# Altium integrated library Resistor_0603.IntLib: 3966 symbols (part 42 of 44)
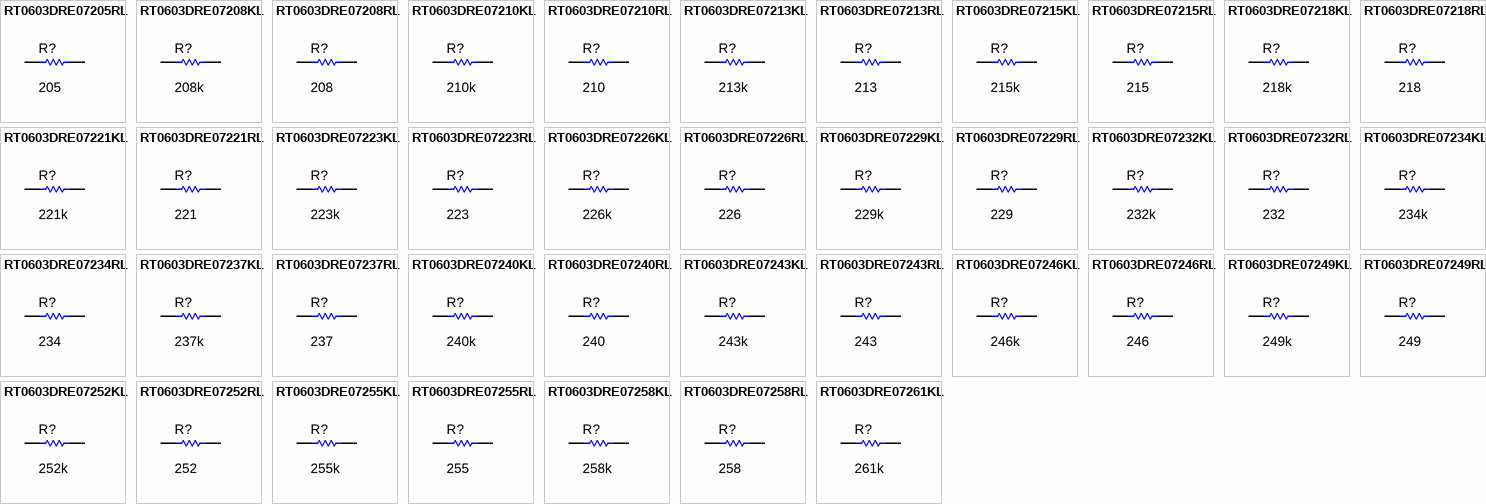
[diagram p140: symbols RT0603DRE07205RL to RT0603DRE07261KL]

## RT0603DRE07240RL
designator R?  ValueDisplayed: 240  (hidden comment: RT0603DRE07240RL)
RES, 240, 0.5%, 0.1 W, 0603; Manufacturer: Yageo America; CompType: Resistor; Value: 240; Value_Code: 240R; Tolerance_%: 0.5; Power_W: 0.1; Value2: 0.1W; VDC_V: 75; TempCo: 50 ppm/C; SizeArea_mm2: 1.28; SizeX_mm: 1.6; SizeY_mm: 0.8; SizeZ_mm: 1; EIA_Code: E192; U/M: EA; AEC Category: Q200
signal-integrity model Resistor
simulation model Resistor
footprint 0603
footprint 0603M
footprint 0603L
footprint 0603_HV
footprint 0603S
pins: 1, 2

## RT0603DRE07243KL
designator R?  ValueDisplayed: 243k  (hidden comment: RT0603DRE07243KL)
RES, 243 k, 0.5%, 0.1 W, 0603; Manufacturer: Yageo America; CompType: Resistor; Value: 243k; Res_ohm: 243000; Tolerance_%: 0.5; Power_W: 0.1; Value2: 0.1W; VDC_V: 75; TempCo: 50 ppm/C; SizeArea_mm2: 1.28; SizeX_mm: 1.6; SizeY_mm: 0.8; SizeZ_mm: 1; EIA_Code: E192; U/M: EA; AEC Category: Q200
signal-integrity model Resistor
simulation model Resistor
footprint 0603
footprint 0603M
footprint 0603L
footprint 0603_HV
footprint 0603S
pins: 1, 2

## RT0603DRE07243RL
designator R?  ValueDisplayed: 243  (hidden comment: RT0603DRE07243RL)
RES, 243, 0.5%, 0.1 W, 0603; Manufacturer: Yageo America; CompType: Resistor; Value: 243; Value_Code: 243R; Tolerance_%: 0.5; Power_W: 0.1; Value2: 0.1W; VDC_V: 75; TempCo: 50 ppm/C; SizeArea_mm2: 1.28; SizeX_mm: 1.6; SizeY_mm: 0.8; SizeZ_mm: 1; EIA_Code: E192; U/M: EA; AEC Category: Q200
signal-integrity model Resistor
simulation model Resistor
footprint 0603
footprint 0603M
footprint 0603L
footprint 0603_HV
footprint 0603S
pins: 1, 2

## RT0603DRE07246KL
designator R?  ValueDisplayed: 246k  (hidden comment: RT0603DRE07246KL)
RES, 246 k, 0.5%, 0.1 W, 0603; Manufacturer: Yageo America; CompType: Resistor; Value: 246k; Res_ohm: 246000; Tolerance_%: 0.5; Power_W: 0.1; Value2: 0.1W; VDC_V: 75; TempCo: 50 ppm/C; SizeArea_mm2: 1.28; SizeX_mm: 1.6; SizeY_mm: 0.8; SizeZ_mm: 1; EIA_Code: E192; U/M: EA; AEC Category: Q200
signal-integrity model Resistor
simulation model Resistor
footprint 0603
footprint 0603M
footprint 0603L
footprint 0603_HV
footprint 0603S
pins: 1, 2

## RT0603DRE07246RL
designator R?  ValueDisplayed: 246  (hidden comment: RT0603DRE07246RL)
RES, 246, 0.5%, 0.1 W, 0603; Manufacturer: Yageo America; CompType: Resistor; Value: 246; Value_Code: 246R; Tolerance_%: 0.5; Power_W: 0.1; Value2: 0.1W; VDC_V: 75; TempCo: 50 ppm/C; SizeArea_mm2: 1.28; SizeX_mm: 1.6; SizeY_mm: 0.8; SizeZ_mm: 1; EIA_Code: E192; U/M: EA; AEC Category: Q200
signal-integrity model Resistor
simulation model Resistor
footprint 0603
footprint 0603M
footprint 0603L
footprint 0603_HV
footprint 0603S
pins: 1, 2

## RT0603DRE07249KL
designator R?  ValueDisplayed: 249k  (hidden comment: RT0603DRE07249KL)
RES, 249 k, 0.5%, 0.1 W, 0603; Manufacturer: Yageo America; CompType: Resistor; Value: 249k; Res_ohm: 249000; Tolerance_%: 0.5; Power_W: 0.1; Value2: 0.1W; VDC_V: 75; TempCo: 50 ppm/C; SizeArea_mm2: 1.28; SizeX_mm: 1.6; SizeY_mm: 0.8; SizeZ_mm: 1; EIA_Code: E192; U/M: EA; AEC Category: Q200
signal-integrity model Resistor
simulation model Resistor
footprint 0603
footprint 0603M
footprint 0603L
footprint 0603_HV
footprint 0603S
pins: 1, 2

## RT0603DRE07249RL
designator R?  ValueDisplayed: 249  (hidden comment: RT0603DRE07249RL)
RES, 249, 0.5%, 0.1 W, 0603; Manufacturer: Yageo America; CompType: Resistor; Value: 249; Value_Code: 249R; Tolerance_%: 0.5; Power_W: 0.1; Value2: 0.1W; VDC_V: 75; TempCo: 50 ppm/C; SizeArea_mm2: 1.28; SizeX_mm: 1.6; SizeY_mm: 0.8; SizeZ_mm: 1; EIA_Code: E192; U/M: EA; AEC Category: Q200
signal-integrity model Resistor
simulation model Resistor
footprint 0603
footprint 0603M
footprint 0603L
footprint 0603_HV
footprint 0603S
pins: 1, 2

## RT0603DRE07252KL
designator R?  ValueDisplayed: 252k  (hidden comment: RT0603DRE07252KL)
RES, 252 k, 0.5%, 0.1 W, 0603; Manufacturer: Yageo America; CompType: Resistor; Value: 252k; Res_ohm: 252000; Tolerance_%: 0.5; Power_W: 0.1; Value2: 0.1W; VDC_V: 75; TempCo: 50 ppm/C; SizeArea_mm2: 1.28; SizeX_mm: 1.6; SizeY_mm: 0.8; SizeZ_mm: 1; EIA_Code: E192; U/M: EA; AEC Category: Q200
signal-integrity model Resistor
simulation model Resistor
footprint 0603
footprint 0603M
footprint 0603L
footprint 0603_HV
footprint 0603S
pins: 1, 2

## RT0603DRE07252RL
designator R?  ValueDisplayed: 252  (hidden comment: RT0603DRE07252RL)
RES, 252, 0.5%, 0.1 W, 0603; Manufacturer: Yageo America; CompType: Resistor; Value: 252; Value_Code: 252R; Tolerance_%: 0.5; Power_W: 0.1; Value2: 0.1W; VDC_V: 75; TempCo: 50 ppm/C; SizeArea_mm2: 1.28; SizeX_mm: 1.6; SizeY_mm: 0.8; SizeZ_mm: 1; EIA_Code: E192; U/M: EA; AEC Category: Q200
signal-integrity model Resistor
simulation model Resistor
footprint 0603
footprint 0603M
footprint 0603L
footprint 0603_HV
footprint 0603S
pins: 1, 2

## RT0603DRE07255KL
designator R?  ValueDisplayed: 255k  (hidden comment: RT0603DRE07255KL)
RES, 255 k, 0.5%, 0.1 W, 0603; Manufacturer: Yageo America; CompType: Resistor; Value: 255k; Res_ohm: 255000; Tolerance_%: 0.5; Power_W: 0.1; Value2: 0.1W; VDC_V: 75; TempCo: 50 ppm/C; SizeArea_mm2: 1.28; SizeX_mm: 1.6; SizeY_mm: 0.8; SizeZ_mm: 1; EIA_Code: E192; U/M: EA; AEC Category: Q200
signal-integrity model Resistor
simulation model Resistor
footprint 0603
footprint 0603M
footprint 0603L
footprint 0603_HV
footprint 0603S
pins: 1, 2

## RT0603DRE07255RL
designator R?  ValueDisplayed: 255  (hidden comment: RT0603DRE07255RL)
RES, 255, 0.5%, 0.1 W, 0603; Manufacturer: Yageo America; CompType: Resistor; Value: 255; Value_Code: 255R; Tolerance_%: 0.5; Power_W: 0.1; Value2: 0.1W; VDC_V: 75; TempCo: 50 ppm/C; SizeArea_mm2: 1.28; SizeX_mm: 1.6; SizeY_mm: 0.8; SizeZ_mm: 1; EIA_Code: E192; U/M: EA; AEC Category: Q200
signal-integrity model Resistor
simulation model Resistor
footprint 0603
footprint 0603M
footprint 0603L
footprint 0603_HV
footprint 0603S
pins: 1, 2

## RT0603DRE07258KL
designator R?  ValueDisplayed: 258k  (hidden comment: RT0603DRE07258KL)
RES, 258 k, 0.5%, 0.1 W, 0603; Manufacturer: Yageo America; CompType: Resistor; Value: 258k; Res_ohm: 258000; Tolerance_%: 0.5; Power_W: 0.1; Value2: 0.1W; VDC_V: 75; TempCo: 50 ppm/C; SizeArea_mm2: 1.28; SizeX_mm: 1.6; SizeY_mm: 0.8; SizeZ_mm: 1; EIA_Code: E192; U/M: EA; AEC Category: Q200
signal-integrity model Resistor
simulation model Resistor
footprint 0603
footprint 0603M
footprint 0603L
footprint 0603_HV
footprint 0603S
pins: 1, 2

## RT0603DRE07258RL
designator R?  ValueDisplayed: 258  (hidden comment: RT0603DRE07258RL)
RES, 258, 0.5%, 0.1 W, 0603; Manufacturer: Yageo America; CompType: Resistor; Value: 258; Value_Code: 258R; Tolerance_%: 0.5; Power_W: 0.1; Value2: 0.1W; VDC_V: 75; TempCo: 50 ppm/C; SizeArea_mm2: 1.28; SizeX_mm: 1.6; SizeY_mm: 0.8; SizeZ_mm: 1; EIA_Code: E192; U/M: EA; AEC Category: Q200
signal-integrity model Resistor
simulation model Resistor
footprint 0603
footprint 0603M
footprint 0603L
footprint 0603_HV
footprint 0603S
pins: 1, 2

## RT0603DRE07261KL
designator R?  ValueDisplayed: 261k  (hidden comment: RT0603DRE07261KL)
RES, 261 k, 0.5%, 0.1 W, 0603; Manufacturer: Yageo America; CompType: Resistor; Value: 261k; Res_ohm: 261000; Tolerance_%: 0.5; Power_W: 0.1; Value2: 0.1W; VDC_V: 75; TempCo: 50 ppm/C; SizeArea_mm2: 1.28; SizeX_mm: 1.6; SizeY_mm: 0.8; SizeZ_mm: 1; EIA_Code: E192; U/M: EA; AEC Category: Q200
signal-integrity model Resistor
simulation model Resistor
footprint 0603
footprint 0603M
footprint 0603L
footprint 0603_HV
footprint 0603S
pins: 1, 2

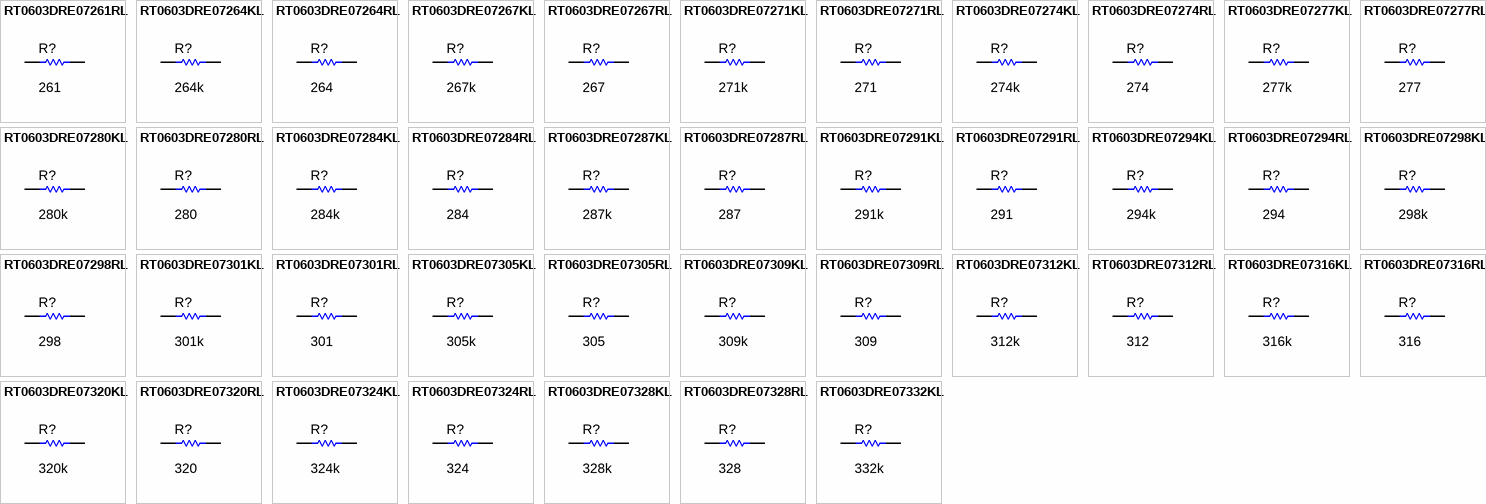
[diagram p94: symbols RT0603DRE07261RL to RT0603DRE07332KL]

## RT0603DRE07261RL
designator R?  ValueDisplayed: 261  (hidden comment: RT0603DRE07261RL)
RES, 261, 0.5%, 0.1 W, 0603; Manufacturer: Yageo America; CompType: Resistor; Value: 261; Value_Code: 261R; Tolerance_%: 0.5; Power_W: 0.1; Value2: 0.1W; VDC_V: 75; TempCo: 50 ppm/C; SizeArea_mm2: 1.28; SizeX_mm: 1.6; SizeY_mm: 0.8; SizeZ_mm: 1; EIA_Code: E192; U/M: EA; AEC Category: Q200
signal-integrity model Resistor
simulation model Resistor
footprint 0603
footprint 0603M
footprint 0603L
footprint 0603_HV
footprint 0603S
pins: 1, 2

## RT0603DRE07264KL
designator R?  ValueDisplayed: 264k  (hidden comment: RT0603DRE07264KL)
RES, 264 k, 0.5%, 0.1 W, 0603; Manufacturer: Yageo America; CompType: Resistor; Value: 264k; Res_ohm: 264000; Tolerance_%: 0.5; Power_W: 0.1; Value2: 0.1W; VDC_V: 75; TempCo: 50 ppm/C; SizeArea_mm2: 1.28; SizeX_mm: 1.6; SizeY_mm: 0.8; SizeZ_mm: 1; EIA_Code: E192; U/M: EA; AEC Category: Q200
signal-integrity model Resistor
simulation model Resistor
footprint 0603
footprint 0603M
footprint 0603L
footprint 0603_HV
footprint 0603S
pins: 1, 2

## RT0603DRE07264RL
designator R?  ValueDisplayed: 264  (hidden comment: RT0603DRE07264RL)
RES, 264, 0.5%, 0.1 W, 0603; Manufacturer: Yageo America; CompType: Resistor; Value: 264; Value_Code: 264R; Tolerance_%: 0.5; Power_W: 0.1; Value2: 0.1W; VDC_V: 75; TempCo: 50 ppm/C; SizeArea_mm2: 1.28; SizeX_mm: 1.6; SizeY_mm: 0.8; SizeZ_mm: 1; EIA_Code: E192; U/M: EA; AEC Category: Q200
signal-integrity model Resistor
simulation model Resistor
footprint 0603
footprint 0603M
footprint 0603L
footprint 0603_HV
footprint 0603S
pins: 1, 2

## RT0603DRE07267KL
designator R?  ValueDisplayed: 267k  (hidden comment: RT0603DRE07267KL)
RES, 267 k, 0.5%, 0.1 W, 0603; Manufacturer: Yageo America; CompType: Resistor; Value: 267k; Res_ohm: 267000; Tolerance_%: 0.5; Power_W: 0.1; Value2: 0.1W; VDC_V: 75; TempCo: 50 ppm/C; SizeArea_mm2: 1.28; SizeX_mm: 1.6; SizeY_mm: 0.8; SizeZ_mm: 1; EIA_Code: E192; U/M: EA; AEC Category: Q200
signal-integrity model Resistor
simulation model Resistor
footprint 0603
footprint 0603M
footprint 0603L
footprint 0603_HV
footprint 0603S
pins: 1, 2

## RT0603DRE07267RL
designator R?  ValueDisplayed: 267  (hidden comment: RT0603DRE07267RL)
RES, 267, 0.5%, 0.1 W, 0603; Manufacturer: Yageo America; CompType: Resistor; Value: 267; Value_Code: 267R; Tolerance_%: 0.5; Power_W: 0.1; Value2: 0.1W; VDC_V: 75; TempCo: 50 ppm/C; SizeArea_mm2: 1.28; SizeX_mm: 1.6; SizeY_mm: 0.8; SizeZ_mm: 1; EIA_Code: E192; U/M: EA; AEC Category: Q200
signal-integrity model Resistor
simulation model Resistor
footprint 0603
footprint 0603M
footprint 0603L
footprint 0603_HV
footprint 0603S
pins: 1, 2

## RT0603DRE07271KL
designator R?  ValueDisplayed: 271k  (hidden comment: RT0603DRE07271KL)
RES, 271 k, 0.5%, 0.1 W, 0603; Manufacturer: Yageo America; CompType: Resistor; Value: 271k; Res_ohm: 271000; Tolerance_%: 0.5; Power_W: 0.1; Value2: 0.1W; VDC_V: 75; TempCo: 50 ppm/C; SizeArea_mm2: 1.28; SizeX_mm: 1.6; SizeY_mm: 0.8; SizeZ_mm: 1; EIA_Code: E192; U/M: EA; AEC Category: Q200
signal-integrity model Resistor
simulation model Resistor
footprint 0603
footprint 0603M
footprint 0603L
footprint 0603_HV
footprint 0603S
pins: 1, 2

## RT0603DRE07271RL
designator R?  ValueDisplayed: 271  (hidden comment: RT0603DRE07271RL)
RES, 271, 0.5%, 0.1 W, 0603; Manufacturer: Yageo America; CompType: Resistor; Value: 271; Value_Code: 271R; Tolerance_%: 0.5; Power_W: 0.1; Value2: 0.1W; VDC_V: 75; TempCo: 50 ppm/C; SizeArea_mm2: 1.28; SizeX_mm: 1.6; SizeY_mm: 0.8; SizeZ_mm: 1; EIA_Code: E192; U/M: EA; AEC Category: Q200
signal-integrity model Resistor
simulation model Resistor
footprint 0603
footprint 0603M
footprint 0603L
footprint 0603_HV
footprint 0603S
pins: 1, 2

## RT0603DRE07274KL
designator R?  ValueDisplayed: 274k  (hidden comment: RT0603DRE07274KL)
RES, 274 k, 0.5%, 0.1 W, 0603; Manufacturer: Yageo America; CompType: Resistor; Value: 274k; Res_ohm: 274000; Tolerance_%: 0.5; Power_W: 0.1; Value2: 0.1W; VDC_V: 75; TempCo: 50 ppm/C; SizeArea_mm2: 1.28; SizeX_mm: 1.6; SizeY_mm: 0.8; SizeZ_mm: 1; EIA_Code: E192; U/M: EA; AEC Category: Q200
signal-integrity model Resistor
simulation model Resistor
footprint 0603
footprint 0603M
footprint 0603L
footprint 0603_HV
footprint 0603S
pins: 1, 2

## RT0603DRE07274RL
designator R?  ValueDisplayed: 274  (hidden comment: RT0603DRE07274RL)
RES, 274, 0.5%, 0.1 W, 0603; Manufacturer: Yageo America; CompType: Resistor; Value: 274; Value_Code: 274R; Tolerance_%: 0.5; Power_W: 0.1; Value2: 0.1W; VDC_V: 75; TempCo: 50 ppm/C; SizeArea_mm2: 1.28; SizeX_mm: 1.6; SizeY_mm: 0.8; SizeZ_mm: 1; EIA_Code: E192; U/M: EA; AEC Category: Q200
signal-integrity model Resistor
simulation model Resistor
footprint 0603
footprint 0603M
footprint 0603L
footprint 0603_HV
footprint 0603S
pins: 1, 2

## RT0603DRE07277KL
designator R?  ValueDisplayed: 277k  (hidden comment: RT0603DRE07277KL)
RES, 277 k, 0.5%, 0.1 W, 0603; Manufacturer: Yageo America; CompType: Resistor; Value: 277k; Res_ohm: 277000; Tolerance_%: 0.5; Power_W: 0.1; Value2: 0.1W; VDC_V: 75; TempCo: 50 ppm/C; SizeArea_mm2: 1.28; SizeX_mm: 1.6; SizeY_mm: 0.8; SizeZ_mm: 1; EIA_Code: E192; U/M: EA; AEC Category: Q200
signal-integrity model Resistor
simulation model Resistor
footprint 0603
footprint 0603M
footprint 0603L
footprint 0603_HV
footprint 0603S
pins: 1, 2

## RT0603DRE07277RL
designator R?  ValueDisplayed: 277  (hidden comment: RT0603DRE07277RL)
RES, 277, 0.5%, 0.1 W, 0603; Manufacturer: Yageo America; CompType: Resistor; Value: 277; Value_Code: 277R; Tolerance_%: 0.5; Power_W: 0.1; Value2: 0.1W; VDC_V: 75; TempCo: 50 ppm/C; SizeArea_mm2: 1.28; SizeX_mm: 1.6; SizeY_mm: 0.8; SizeZ_mm: 1; EIA_Code: E192; U/M: EA; AEC Category: Q200
signal-integrity model Resistor
simulation model Resistor
footprint 0603
footprint 0603M
footprint 0603L
footprint 0603_HV
footprint 0603S
pins: 1, 2

## RT0603DRE07280KL
designator R?  ValueDisplayed: 280k  (hidden comment: RT0603DRE07280KL)
RES, 280 k, 0.5%, 0.1 W, 0603; Manufacturer: Yageo America; CompType: Resistor; Value: 280k; Res_ohm: 280000; Tolerance_%: 0.5; Power_W: 0.1; Value2: 0.1W; VDC_V: 75; TempCo: 50 ppm/C; SizeArea_mm2: 1.28; SizeX_mm: 1.6; SizeY_mm: 0.8; SizeZ_mm: 1; EIA_Code: E192; U/M: EA; AEC Category: Q200
signal-integrity model Resistor
simulation model Resistor
footprint 0603
footprint 0603M
footprint 0603L
footprint 0603_HV
footprint 0603S
pins: 1, 2

## RT0603DRE07280RL
designator R?  ValueDisplayed: 280  (hidden comment: RT0603DRE07280RL)
RES, 280, 0.5%, 0.1 W, 0603; Manufacturer: Yageo America; CompType: Resistor; Value: 280; Value_Code: 280R; Tolerance_%: 0.5; Power_W: 0.1; Value2: 0.1W; VDC_V: 75; TempCo: 50 ppm/C; SizeArea_mm2: 1.28; SizeX_mm: 1.6; SizeY_mm: 0.8; SizeZ_mm: 1; EIA_Code: E192; U/M: EA; AEC Category: Q200
signal-integrity model Resistor
simulation model Resistor
footprint 0603
footprint 0603M
footprint 0603L
footprint 0603_HV
footprint 0603S
pins: 1, 2

## RT0603DRE07284KL
designator R?  ValueDisplayed: 284k  (hidden comment: RT0603DRE07284KL)
RES, 284 k, 0.5%, 0.1 W, 0603; Manufacturer: Yageo America; CompType: Resistor; Value: 284k; Res_ohm: 284000; Tolerance_%: 0.5; Power_W: 0.1; Value2: 0.1W; VDC_V: 75; TempCo: 50 ppm/C; SizeArea_mm2: 1.28; SizeX_mm: 1.6; SizeY_mm: 0.8; SizeZ_mm: 1; EIA_Code: E192; U/M: EA; AEC Category: Q200
signal-integrity model Resistor
simulation model Resistor
footprint 0603
footprint 0603M
footprint 0603L
footprint 0603_HV
footprint 0603S
pins: 1, 2

## RT0603DRE07284RL
designator R?  ValueDisplayed: 284  (hidden comment: RT0603DRE07284RL)
RES, 284, 0.5%, 0.1 W, 0603; Manufacturer: Yageo America; CompType: Resistor; Value: 284; Value_Code: 284R; Tolerance_%: 0.5; Power_W: 0.1; Value2: 0.1W; VDC_V: 75; TempCo: 50 ppm/C; SizeArea_mm2: 1.28; SizeX_mm: 1.6; SizeY_mm: 0.8; SizeZ_mm: 1; EIA_Code: E192; U/M: EA; AEC Category: Q200
signal-integrity model Resistor
simulation model Resistor
footprint 0603
footprint 0603M
footprint 0603L
footprint 0603_HV
footprint 0603S
pins: 1, 2

## RT0603DRE07287KL
designator R?  ValueDisplayed: 287k  (hidden comment: RT0603DRE07287KL)
RES, 287 k, 0.5%, 0.1 W, 0603; Manufacturer: Yageo America; CompType: Resistor; Value: 287k; Res_ohm: 287000; Tolerance_%: 0.5; Power_W: 0.1; Value2: 0.1W; VDC_V: 75; TempCo: 50 ppm/C; SizeArea_mm2: 1.28; SizeX_mm: 1.6; SizeY_mm: 0.8; SizeZ_mm: 1; EIA_Code: E192; U/M: EA; AEC Category: Q200
signal-integrity model Resistor
simulation model Resistor
footprint 0603
footprint 0603M
footprint 0603L
footprint 0603_HV
footprint 0603S
pins: 1, 2

## RT0603DRE07287RL
designator R?  ValueDisplayed: 287  (hidden comment: RT0603DRE07287RL)
RES, 287, 0.5%, 0.1 W, 0603; Manufacturer: Yageo America; CompType: Resistor; Value: 287; Value_Code: 287R; Tolerance_%: 0.5; Power_W: 0.1; Value2: 0.1W; VDC_V: 75; TempCo: 50 ppm/C; SizeArea_mm2: 1.28; SizeX_mm: 1.6; SizeY_mm: 0.8; SizeZ_mm: 1; EIA_Code: E192; U/M: EA; AEC Category: Q200
signal-integrity model Resistor
simulation model Resistor
footprint 0603
footprint 0603M
footprint 0603L
footprint 0603_HV
footprint 0603S
pins: 1, 2

## RT0603DRE07291KL
designator R?  ValueDisplayed: 291k  (hidden comment: RT0603DRE07291KL)
RES, 291 k, 0.5%, 0.1 W, 0603; Manufacturer: Yageo America; CompType: Resistor; Value: 291k; Res_ohm: 291000; Tolerance_%: 0.5; Power_W: 0.1; Value2: 0.1W; VDC_V: 75; TempCo: 50 ppm/C; SizeArea_mm2: 1.28; SizeX_mm: 1.6; SizeY_mm: 0.8; SizeZ_mm: 1; EIA_Code: E192; U/M: EA; AEC Category: Q200
signal-integrity model Resistor
simulation model Resistor
footprint 0603
footprint 0603M
footprint 0603L
footprint 0603_HV
footprint 0603S
pins: 1, 2

## RT0603DRE07291RL
designator R?  ValueDisplayed: 291  (hidden comment: RT0603DRE07291RL)
RES, 291, 0.5%, 0.1 W, 0603; Manufacturer: Yageo America; CompType: Resistor; Value: 291; Value_Code: 291R; Tolerance_%: 0.5; Power_W: 0.1; Value2: 0.1W; VDC_V: 75; TempCo: 50 ppm/C; SizeArea_mm2: 1.28; SizeX_mm: 1.6; SizeY_mm: 0.8; SizeZ_mm: 1; EIA_Code: E192; U/M: EA; AEC Category: Q200
signal-integrity model Resistor
simulation model Resistor
footprint 0603
footprint 0603M
footprint 0603L
footprint 0603_HV
footprint 0603S
pins: 1, 2

## RT0603DRE07294KL
designator R?  ValueDisplayed: 294k  (hidden comment: RT0603DRE07294KL)
RES, 294 k, 0.5%, 0.1 W, 0603; Manufacturer: Yageo America; CompType: Resistor; Value: 294k; Res_ohm: 294000; Tolerance_%: 0.5; Power_W: 0.1; Value2: 0.1W; VDC_V: 75; TempCo: 50 ppm/C; SizeArea_mm2: 1.28; SizeX_mm: 1.6; SizeY_mm: 0.8; SizeZ_mm: 1; EIA_Code: E192; U/M: EA; AEC Category: Q200
signal-integrity model Resistor
simulation model Resistor
footprint 0603
footprint 0603M
footprint 0603L
footprint 0603_HV
footprint 0603S
pins: 1, 2

## RT0603DRE07294RL
designator R?  ValueDisplayed: 294  (hidden comment: RT0603DRE07294RL)
RES, 294, 0.5%, 0.1 W, 0603; Manufacturer: Yageo America; CompType: Resistor; Value: 294; Value_Code: 294R; Tolerance_%: 0.5; Power_W: 0.1; Value2: 0.1W; VDC_V: 75; TempCo: 50 ppm/C; SizeArea_mm2: 1.28; SizeX_mm: 1.6; SizeY_mm: 0.8; SizeZ_mm: 1; EIA_Code: E192; U/M: EA; AEC Category: Q200
signal-integrity model Resistor
simulation model Resistor
footprint 0603
footprint 0603M
footprint 0603L
footprint 0603_HV
footprint 0603S
pins: 1, 2

## RT0603DRE07298KL
designator R?  ValueDisplayed: 298k  (hidden comment: RT0603DRE07298KL)
RES, 298 k, 0.5%, 0.1 W, 0603; Manufacturer: Yageo America; CompType: Resistor; Value: 298k; Res_ohm: 298000; Tolerance_%: 0.5; Power_W: 0.1; Value2: 0.1W; VDC_V: 75; TempCo: 50 ppm/C; SizeArea_mm2: 1.28; SizeX_mm: 1.6; SizeY_mm: 0.8; SizeZ_mm: 1; EIA_Code: E192; U/M: EA; AEC Category: Q200
signal-integrity model Resistor
simulation model Resistor
footprint 0603
footprint 0603M
footprint 0603L
footprint 0603_HV
footprint 0603S
pins: 1, 2

## RT0603DRE07298RL
designator R?  ValueDisplayed: 298  (hidden comment: RT0603DRE07298RL)
RES, 298, 0.5%, 0.1 W, 0603; Manufacturer: Yageo America; CompType: Resistor; Value: 298; Value_Code: 298R; Tolerance_%: 0.5; Power_W: 0.1; Value2: 0.1W; VDC_V: 75; TempCo: 50 ppm/C; SizeArea_mm2: 1.28; SizeX_mm: 1.6; SizeY_mm: 0.8; SizeZ_mm: 1; EIA_Code: E192; U/M: EA; AEC Category: Q200
signal-integrity model Resistor
simulation model Resistor
footprint 0603
footprint 0603M
footprint 0603L
footprint 0603_HV
footprint 0603S
pins: 1, 2

## RT0603DRE07301KL
designator R?  ValueDisplayed: 301k  (hidden comment: RT0603DRE07301KL)
RES, 301 k, 0.5%, 0.1 W, 0603; Manufacturer: Yageo America; CompType: Resistor; Value: 301k; Res_ohm: 301000; Tolerance_%: 0.5; Power_W: 0.1; Value2: 0.1W; VDC_V: 75; TempCo: 50 ppm/C; SizeArea_mm2: 1.28; SizeX_mm: 1.6; SizeY_mm: 0.8; SizeZ_mm: 1; EIA_Code: E192; U/M: EA; AEC Category: Q200
signal-integrity model Resistor
simulation model Resistor
footprint 0603
footprint 0603M
footprint 0603L
footprint 0603_HV
footprint 0603S
pins: 1, 2

## RT0603DRE07301RL
designator R?  ValueDisplayed: 301  (hidden comment: RT0603DRE07301RL)
RES, 301, 0.5%, 0.1 W, 0603; Manufacturer: Yageo America; CompType: Resistor; Value: 301; Value_Code: 301R; Tolerance_%: 0.5; Power_W: 0.1; Value2: 0.1W; VDC_V: 75; TempCo: 50 ppm/C; SizeArea_mm2: 1.28; SizeX_mm: 1.6; SizeY_mm: 0.8; SizeZ_mm: 1; EIA_Code: E192; U/M: EA; AEC Category: Q200
signal-integrity model Resistor
simulation model Resistor
footprint 0603
footprint 0603M
footprint 0603L
footprint 0603_HV
footprint 0603S
pins: 1, 2

## RT0603DRE07305KL
designator R?  ValueDisplayed: 305k  (hidden comment: RT0603DRE07305KL)
RES, 305 k, 0.5%, 0.1 W, 0603; Manufacturer: Yageo America; CompType: Resistor; Value: 305k; Res_ohm: 305000; Tolerance_%: 0.5; Power_W: 0.1; Value2: 0.1W; VDC_V: 75; TempCo: 50 ppm/C; SizeArea_mm2: 1.28; SizeX_mm: 1.6; SizeY_mm: 0.8; SizeZ_mm: 1; EIA_Code: E192; U/M: EA; AEC Category: Q200
signal-integrity model Resistor
simulation model Resistor
footprint 0603
footprint 0603M
footprint 0603L
footprint 0603_HV
footprint 0603S
pins: 1, 2

## RT0603DRE07305RL
designator R?  ValueDisplayed: 305  (hidden comment: RT0603DRE07305RL)
RES, 305, 0.5%, 0.1 W, 0603; Manufacturer: Yageo America; CompType: Resistor; Value: 305; Value_Code: 305R; Tolerance_%: 0.5; Power_W: 0.1; Value2: 0.1W; VDC_V: 75; TempCo: 50 ppm/C; SizeArea_mm2: 1.28; SizeX_mm: 1.6; SizeY_mm: 0.8; SizeZ_mm: 1; EIA_Code: E192; U/M: EA; AEC Category: Q200
signal-integrity model Resistor
simulation model Resistor
footprint 0603
footprint 0603M
footprint 0603L
footprint 0603_HV
footprint 0603S
pins: 1, 2

## RT0603DRE07309KL
designator R?  ValueDisplayed: 309k  (hidden comment: RT0603DRE07309KL)
RES, 309 k, 0.5%, 0.1 W, 0603; Manufacturer: Yageo America; CompType: Resistor; Value: 309k; Res_ohm: 309000; Tolerance_%: 0.5; Power_W: 0.1; Value2: 0.1W; VDC_V: 75; TempCo: 50 ppm/C; SizeArea_mm2: 1.28; SizeX_mm: 1.6; SizeY_mm: 0.8; SizeZ_mm: 1; EIA_Code: E192; U/M: EA; AEC Category: Q200
signal-integrity model Resistor
simulation model Resistor
footprint 0603
footprint 0603M
footprint 0603L
footprint 0603_HV
footprint 0603S
pins: 1, 2

## RT0603DRE07309RL
designator R?  ValueDisplayed: 309  (hidden comment: RT0603DRE07309RL)
RES, 309, 0.5%, 0.1 W, 0603; Manufacturer: Yageo America; CompType: Resistor; Value: 309; Value_Code: 309R; Tolerance_%: 0.5; Power_W: 0.1; Value2: 0.1W; VDC_V: 75; TempCo: 50 ppm/C; SizeArea_mm2: 1.28; SizeX_mm: 1.6; SizeY_mm: 0.8; SizeZ_mm: 1; EIA_Code: E192; U/M: EA; AEC Category: Q200
signal-integrity model Resistor
simulation model Resistor
footprint 0603
footprint 0603M
footprint 0603L
footprint 0603_HV
footprint 0603S
pins: 1, 2

## RT0603DRE07312KL
designator R?  ValueDisplayed: 312k  (hidden comment: RT0603DRE07312KL)
RES, 312 k, 0.5%, 0.1 W, 0603; Manufacturer: Yageo America; CompType: Resistor; Value: 312k; Res_ohm: 312000; Tolerance_%: 0.5; Power_W: 0.1; Value2: 0.1W; VDC_V: 75; TempCo: 50 ppm/C; SizeArea_mm2: 1.28; SizeX_mm: 1.6; SizeY_mm: 0.8; SizeZ_mm: 1; EIA_Code: E192; U/M: EA; AEC Category: Q200
signal-integrity model Resistor
simulation model Resistor
footprint 0603
footprint 0603M
footprint 0603L
footprint 0603_HV
footprint 0603S
pins: 1, 2

## RT0603DRE07312RL
designator R?  ValueDisplayed: 312  (hidden comment: RT0603DRE07312RL)
RES, 312, 0.5%, 0.1 W, 0603; Manufacturer: Yageo America; CompType: Resistor; Value: 312; Value_Code: 312R; Tolerance_%: 0.5; Power_W: 0.1; Value2: 0.1W; VDC_V: 75; TempCo: 50 ppm/C; SizeArea_mm2: 1.28; SizeX_mm: 1.6; SizeY_mm: 0.8; SizeZ_mm: 1; EIA_Code: E192; U/M: EA; AEC Category: Q200
signal-integrity model Resistor
simulation model Resistor
footprint 0603
footprint 0603M
footprint 0603L
footprint 0603_HV
footprint 0603S
pins: 1, 2

## RT0603DRE07316KL
designator R?  ValueDisplayed: 316k  (hidden comment: RT0603DRE07316KL)
RES, 316 k, 0.5%, 0.1 W, 0603; Manufacturer: Yageo America; CompType: Resistor; Value: 316k; Res_ohm: 316000; Tolerance_%: 0.5; Power_W: 0.1; Value2: 0.1W; VDC_V: 75; TempCo: 50 ppm/C; SizeArea_mm2: 1.28; SizeX_mm: 1.6; SizeY_mm: 0.8; SizeZ_mm: 1; EIA_Code: E192; U/M: EA; AEC Category: Q200
signal-integrity model Resistor
simulation model Resistor
footprint 0603
footprint 0603M
footprint 0603L
footprint 0603_HV
footprint 0603S
pins: 1, 2

## RT0603DRE07316RL
designator R?  ValueDisplayed: 316  (hidden comment: RT0603DRE07316RL)
RES, 316, 0.5%, 0.1 W, 0603; Manufacturer: Yageo America; CompType: Resistor; Value: 316; Value_Code: 316R; Tolerance_%: 0.5; Power_W: 0.1; Value2: 0.1W; VDC_V: 75; TempCo: 50 ppm/C; SizeArea_mm2: 1.28; SizeX_mm: 1.6; SizeY_mm: 0.8; SizeZ_mm: 1; EIA_Code: E192; U/M: EA; AEC Category: Q200
signal-integrity model Resistor
simulation model Resistor
footprint 0603
footprint 0603M
footprint 0603L
footprint 0603_HV
footprint 0603S
pins: 1, 2

## RT0603DRE07320KL
designator R?  ValueDisplayed: 320k  (hidden comment: RT0603DRE07320KL)
RES, 320 k, 0.5%, 0.1 W, 0603; Manufacturer: Yageo America; CompType: Resistor; Value: 320k; Res_ohm: 320000; Tolerance_%: 0.5; Power_W: 0.1; Value2: 0.1W; VDC_V: 75; TempCo: 50 ppm/C; SizeArea_mm2: 1.28; SizeX_mm: 1.6; SizeY_mm: 0.8; SizeZ_mm: 1; EIA_Code: E192; U/M: EA; AEC Category: Q200
signal-integrity model Resistor
simulation model Resistor
footprint 0603
footprint 0603M
footprint 0603L
footprint 0603_HV
footprint 0603S
pins: 1, 2

## RT0603DRE07320RL
designator R?  ValueDisplayed: 320  (hidden comment: RT0603DRE07320RL)
RES, 320, 0.5%, 0.1 W, 0603; Manufacturer: Yageo America; CompType: Resistor; Value: 320; Value_Code: 320R; Tolerance_%: 0.5; Power_W: 0.1; Value2: 0.1W; VDC_V: 75; TempCo: 50 ppm/C; SizeArea_mm2: 1.28; SizeX_mm: 1.6; SizeY_mm: 0.8; SizeZ_mm: 1; EIA_Code: E192; U/M: EA; AEC Category: Q200
signal-integrity model Resistor
simulation model Resistor
footprint 0603
footprint 0603M
footprint 0603L
footprint 0603_HV
footprint 0603S
pins: 1, 2

## RT0603DRE07324KL
designator R?  ValueDisplayed: 324k  (hidden comment: RT0603DRE07324KL)
RES, 324 k, 0.5%, 0.1 W, 0603; Manufacturer: Yageo America; CompType: Resistor; Value: 324k; Res_ohm: 324000; Tolerance_%: 0.5; Power_W: 0.1; Value2: 0.1W; VDC_V: 75; TempCo: 50 ppm/C; SizeArea_mm2: 1.28; SizeX_mm: 1.6; SizeY_mm: 0.8; SizeZ_mm: 1; EIA_Code: E192; U/M: EA; AEC Category: Q200
signal-integrity model Resistor
simulation model Resistor
footprint 0603
footprint 0603M
footprint 0603L
footprint 0603_HV
footprint 0603S
pins: 1, 2

## RT0603DRE07324RL
designator R?  ValueDisplayed: 324  (hidden comment: RT0603DRE07324RL)
RES, 324, 0.5%, 0.1 W, 0603; Manufacturer: Yageo America; CompType: Resistor; Value: 324; Value_Code: 324R; Tolerance_%: 0.5; Power_W: 0.1; Value2: 0.1W; VDC_V: 75; TempCo: 50 ppm/C; SizeArea_mm2: 1.28; SizeX_mm: 1.6; SizeY_mm: 0.8; SizeZ_mm: 1; EIA_Code: E192; U/M: EA; AEC Category: Q200
signal-integrity model Resistor
simulation model Resistor
footprint 0603
footprint 0603M
footprint 0603L
footprint 0603_HV
footprint 0603S
pins: 1, 2

## RT0603DRE07328KL
designator R?  ValueDisplayed: 328k  (hidden comment: RT0603DRE07328KL)
RES, 328 k, 0.5%, 0.1 W, 0603; Manufacturer: Yageo America; CompType: Resistor; Value: 328k; Res_ohm: 328000; Tolerance_%: 0.5; Power_W: 0.1; Value2: 0.1W; VDC_V: 75; TempCo: 50 ppm/C; SizeArea_mm2: 1.28; SizeX_mm: 1.6; SizeY_mm: 0.8; SizeZ_mm: 1; EIA_Code: E192; U/M: EA; AEC Category: Q200
signal-integrity model Resistor
simulation model Resistor
footprint 0603
footprint 0603M
footprint 0603L
footprint 0603_HV
footprint 0603S
pins: 1, 2

## RT0603DRE07328RL
designator R?  ValueDisplayed: 328  (hidden comment: RT0603DRE07328RL)
RES, 328, 0.5%, 0.1 W, 0603; Manufacturer: Yageo America; CompType: Resistor; Value: 328; Value_Code: 328R; Tolerance_%: 0.5; Power_W: 0.1; Value2: 0.1W; VDC_V: 75; TempCo: 50 ppm/C; SizeArea_mm2: 1.28; SizeX_mm: 1.6; SizeY_mm: 0.8; SizeZ_mm: 1; EIA_Code: E192; U/M: EA; AEC Category: Q200
signal-integrity model Resistor
simulation model Resistor
footprint 0603
footprint 0603M
footprint 0603L
footprint 0603_HV
footprint 0603S
pins: 1, 2

## RT0603DRE07332KL
designator R?  ValueDisplayed: 332k  (hidden comment: RT0603DRE07332KL)
RES, 332 k, 0.5%, 0.1 W, 0603; Manufacturer: Yageo America; CompType: Resistor; Value: 332k; Res_ohm: 332000; Tolerance_%: 0.5; Power_W: 0.1; Value2: 0.1W; VDC_V: 75; TempCo: 50 ppm/C; SizeArea_mm2: 1.28; SizeX_mm: 1.6; SizeY_mm: 0.8; SizeZ_mm: 1; EIA_Code: E192; U/M: EA; AEC Category: Q200; Green_Lifecycle: Active; Green_REACh: Passed
signal-integrity model Resistor
simulation model Resistor
footprint 0603
footprint 0603M
footprint 0603L
footprint 0603_HV
footprint 0603S
pins: 1, 2

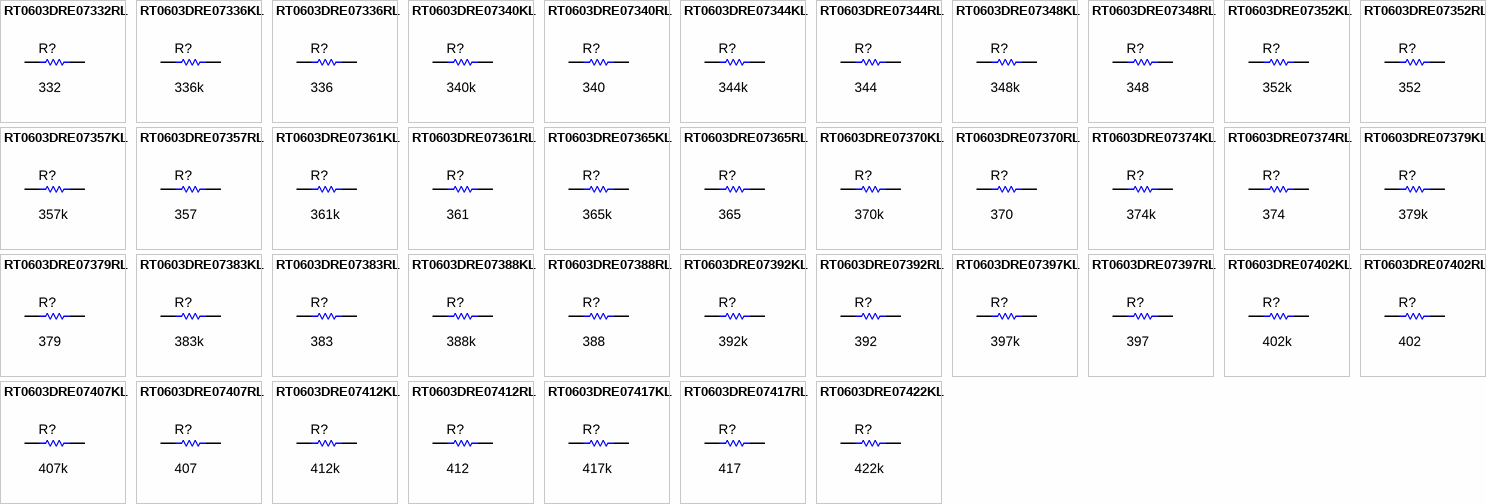
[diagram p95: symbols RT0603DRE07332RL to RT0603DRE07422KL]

## RT0603DRE07332RL
designator R?  ValueDisplayed: 332  (hidden comment: RT0603DRE07332RL)
RES, 332, 0.5%, 0.1 W, 0603; Manufacturer: Yageo America; CompType: Resistor; Value: 332; Value_Code: 332R; Tolerance_%: 0.5; Power_W: 0.1; Value2: 0.1W; VDC_V: 75; TempCo: 50 ppm/C; SizeArea_mm2: 1.28; SizeX_mm: 1.6; SizeY_mm: 0.8; SizeZ_mm: 1; EIA_Code: E192; U/M: EA; AEC Category: Q200
signal-integrity model Resistor
simulation model Resistor
footprint 0603
footprint 0603M
footprint 0603L
footprint 0603_HV
footprint 0603S
pins: 1, 2

## RT0603DRE07336KL
designator R?  ValueDisplayed: 336k  (hidden comment: RT0603DRE07336KL)
RES, 336 k, 0.5%, 0.1 W, 0603; Manufacturer: Yageo America; CompType: Resistor; Value: 336k; Res_ohm: 336000; Tolerance_%: 0.5; Power_W: 0.1; Value2: 0.1W; VDC_V: 75; TempCo: 50 ppm/C; SizeArea_mm2: 1.28; SizeX_mm: 1.6; SizeY_mm: 0.8; SizeZ_mm: 1; EIA_Code: E192; U/M: EA; AEC Category: Q200
signal-integrity model Resistor
simulation model Resistor
footprint 0603
footprint 0603M
footprint 0603L
footprint 0603_HV
footprint 0603S
pins: 1, 2

## RT0603DRE07336RL
designator R?  ValueDisplayed: 336  (hidden comment: RT0603DRE07336RL)
RES, 336, 0.5%, 0.1 W, 0603; Manufacturer: Yageo America; CompType: Resistor; Value: 336; Value_Code: 336R; Tolerance_%: 0.5; Power_W: 0.1; Value2: 0.1W; VDC_V: 75; TempCo: 50 ppm/C; SizeArea_mm2: 1.28; SizeX_mm: 1.6; SizeY_mm: 0.8; SizeZ_mm: 1; EIA_Code: E192; U/M: EA; AEC Category: Q200
signal-integrity model Resistor
simulation model Resistor
footprint 0603
footprint 0603M
footprint 0603L
footprint 0603_HV
footprint 0603S
pins: 1, 2

## RT0603DRE07340KL
designator R?  ValueDisplayed: 340k  (hidden comment: RT0603DRE07340KL)
RES, 340 k, 0.5%, 0.1 W, 0603; Manufacturer: Yageo America; CompType: Resistor; Value: 340k; Res_ohm: 340000; Tolerance_%: 0.5; Power_W: 0.1; Value2: 0.1W; VDC_V: 75; TempCo: 50 ppm/C; SizeArea_mm2: 1.28; SizeX_mm: 1.6; SizeY_mm: 0.8; SizeZ_mm: 1; EIA_Code: E192; U/M: EA; AEC Category: Q200
signal-integrity model Resistor
simulation model Resistor
footprint 0603
footprint 0603M
footprint 0603L
footprint 0603_HV
footprint 0603S
pins: 1, 2

## RT0603DRE07340RL
designator R?  ValueDisplayed: 340  (hidden comment: RT0603DRE07340RL)
RES, 340, 0.5%, 0.1 W, 0603; Manufacturer: Yageo America; CompType: Resistor; Value: 340; Value_Code: 340R; Tolerance_%: 0.5; Power_W: 0.1; Value2: 0.1W; VDC_V: 75; TempCo: 50 ppm/C; SizeArea_mm2: 1.28; SizeX_mm: 1.6; SizeY_mm: 0.8; SizeZ_mm: 1; EIA_Code: E192; U/M: EA; AEC Category: Q200
signal-integrity model Resistor
simulation model Resistor
footprint 0603
footprint 0603M
footprint 0603L
footprint 0603_HV
footprint 0603S
pins: 1, 2

## RT0603DRE07344KL
designator R?  ValueDisplayed: 344k  (hidden comment: RT0603DRE07344KL)
RES, 344 k, 0.5%, 0.1 W, 0603; Manufacturer: Yageo America; CompType: Resistor; Value: 344k; Res_ohm: 344000; Tolerance_%: 0.5; Power_W: 0.1; Value2: 0.1W; VDC_V: 75; TempCo: 50 ppm/C; SizeArea_mm2: 1.28; SizeX_mm: 1.6; SizeY_mm: 0.8; SizeZ_mm: 1; EIA_Code: E192; U/M: EA; AEC Category: Q200
signal-integrity model Resistor
simulation model Resistor
footprint 0603
footprint 0603M
footprint 0603L
footprint 0603_HV
footprint 0603S
pins: 1, 2

## RT0603DRE07344RL
designator R?  ValueDisplayed: 344  (hidden comment: RT0603DRE07344RL)
RES, 344, 0.5%, 0.1 W, 0603; Manufacturer: Yageo America; CompType: Resistor; Value: 344; Value_Code: 344R; Tolerance_%: 0.5; Power_W: 0.1; Value2: 0.1W; VDC_V: 75; TempCo: 50 ppm/C; SizeArea_mm2: 1.28; SizeX_mm: 1.6; SizeY_mm: 0.8; SizeZ_mm: 1; EIA_Code: E192; U/M: EA; AEC Category: Q200
signal-integrity model Resistor
simulation model Resistor
footprint 0603
footprint 0603M
footprint 0603L
footprint 0603_HV
footprint 0603S
pins: 1, 2

## RT0603DRE07348KL
designator R?  ValueDisplayed: 348k  (hidden comment: RT0603DRE07348KL)
RES, 348 k, 0.5%, 0.1 W, 0603; Manufacturer: Yageo America; CompType: Resistor; Value: 348k; Res_ohm: 348000; Tolerance_%: 0.5; Power_W: 0.1; Value2: 0.1W; VDC_V: 75; TempCo: 50 ppm/C; SizeArea_mm2: 1.28; SizeX_mm: 1.6; SizeY_mm: 0.8; SizeZ_mm: 1; EIA_Code: E192; U/M: EA; AEC Category: Q200
signal-integrity model Resistor
simulation model Resistor
footprint 0603
footprint 0603M
footprint 0603L
footprint 0603_HV
footprint 0603S
pins: 1, 2

## RT0603DRE07348RL
designator R?  ValueDisplayed: 348  (hidden comment: RT0603DRE07348RL)
RES, 348, 0.5%, 0.1 W, 0603; Manufacturer: Yageo America; CompType: Resistor; Value: 348; Value_Code: 348R; Tolerance_%: 0.5; Power_W: 0.1; Value2: 0.1W; VDC_V: 75; TempCo: 50 ppm/C; SizeArea_mm2: 1.28; SizeX_mm: 1.6; SizeY_mm: 0.8; SizeZ_mm: 1; EIA_Code: E192; U/M: EA; AEC Category: Q200
signal-integrity model Resistor
simulation model Resistor
footprint 0603
footprint 0603M
footprint 0603L
footprint 0603_HV
footprint 0603S
pins: 1, 2

## RT0603DRE07352KL
designator R?  ValueDisplayed: 352k  (hidden comment: RT0603DRE07352KL)
RES, 352 k, 0.5%, 0.1 W, 0603; Manufacturer: Yageo America; CompType: Resistor; Value: 352k; Res_ohm: 352000; Tolerance_%: 0.5; Power_W: 0.1; Value2: 0.1W; VDC_V: 75; TempCo: 50 ppm/C; SizeArea_mm2: 1.28; SizeX_mm: 1.6; SizeY_mm: 0.8; SizeZ_mm: 1; EIA_Code: E192; U/M: EA; AEC Category: Q200
signal-integrity model Resistor
simulation model Resistor
footprint 0603
footprint 0603M
footprint 0603L
footprint 0603_HV
footprint 0603S
pins: 1, 2

## RT0603DRE07352RL
designator R?  ValueDisplayed: 352  (hidden comment: RT0603DRE07352RL)
RES, 352, 0.5%, 0.1 W, 0603; Manufacturer: Yageo America; CompType: Resistor; Value: 352; Value_Code: 352R; Tolerance_%: 0.5; Power_W: 0.1; Value2: 0.1W; VDC_V: 75; TempCo: 50 ppm/C; SizeArea_mm2: 1.28; SizeX_mm: 1.6; SizeY_mm: 0.8; SizeZ_mm: 1; EIA_Code: E192; U/M: EA; AEC Category: Q200
signal-integrity model Resistor
simulation model Resistor
footprint 0603
footprint 0603M
footprint 0603L
footprint 0603_HV
footprint 0603S
pins: 1, 2

## RT0603DRE07357KL
designator R?  ValueDisplayed: 357k  (hidden comment: RT0603DRE07357KL)
RES, 357 k, 0.5%, 0.1 W, 0603; Manufacturer: Yageo America; CompType: Resistor; Value: 357k; Res_ohm: 357000; Tolerance_%: 0.5; Power_W: 0.1; Value2: 0.1W; VDC_V: 75; TempCo: 50 ppm/C; SizeArea_mm2: 1.28; SizeX_mm: 1.6; SizeY_mm: 0.8; SizeZ_mm: 1; EIA_Code: E192; U/M: EA; AEC Category: Q200
signal-integrity model Resistor
simulation model Resistor
footprint 0603
footprint 0603M
footprint 0603L
footprint 0603_HV
footprint 0603S
pins: 1, 2

## RT0603DRE07357RL
designator R?  ValueDisplayed: 357  (hidden comment: RT0603DRE07357RL)
RES, 357, 0.5%, 0.1 W, 0603; Manufacturer: Yageo America; CompType: Resistor; Value: 357; Value_Code: 357R; Tolerance_%: 0.5; Power_W: 0.1; Value2: 0.1W; VDC_V: 75; TempCo: 50 ppm/C; SizeArea_mm2: 1.28; SizeX_mm: 1.6; SizeY_mm: 0.8; SizeZ_mm: 1; EIA_Code: E192; U/M: EA; AEC Category: Q200
signal-integrity model Resistor
simulation model Resistor
footprint 0603
footprint 0603M
footprint 0603L
footprint 0603_HV
footprint 0603S
pins: 1, 2

## RT0603DRE07361KL
designator R?  ValueDisplayed: 361k  (hidden comment: RT0603DRE07361KL)
RES, 361 k, 0.5%, 0.1 W, 0603; Manufacturer: Yageo America; CompType: Resistor; Value: 361k; Res_ohm: 361000; Tolerance_%: 0.5; Power_W: 0.1; Value2: 0.1W; VDC_V: 75; TempCo: 50 ppm/C; SizeArea_mm2: 1.28; SizeX_mm: 1.6; SizeY_mm: 0.8; SizeZ_mm: 1; EIA_Code: E192; U/M: EA; AEC Category: Q200
signal-integrity model Resistor
simulation model Resistor
footprint 0603
footprint 0603M
footprint 0603L
footprint 0603_HV
footprint 0603S
pins: 1, 2

## RT0603DRE07361RL
designator R?  ValueDisplayed: 361  (hidden comment: RT0603DRE07361RL)
RES, 361, 0.5%, 0.1 W, 0603; Manufacturer: Yageo America; CompType: Resistor; Value: 361; Value_Code: 361R; Tolerance_%: 0.5; Power_W: 0.1; Value2: 0.1W; VDC_V: 75; TempCo: 50 ppm/C; SizeArea_mm2: 1.28; SizeX_mm: 1.6; SizeY_mm: 0.8; SizeZ_mm: 1; EIA_Code: E192; U/M: EA; AEC Category: Q200
signal-integrity model Resistor
simulation model Resistor
footprint 0603
footprint 0603M
footprint 0603L
footprint 0603_HV
footprint 0603S
pins: 1, 2

## RT0603DRE07365KL
designator R?  ValueDisplayed: 365k  (hidden comment: RT0603DRE07365KL)
RES, 365 k, 0.5%, 0.1 W, 0603; Manufacturer: Yageo America; CompType: Resistor; Value: 365k; Res_ohm: 365000; Tolerance_%: 0.5; Power_W: 0.1; Value2: 0.1W; VDC_V: 75; TempCo: 50 ppm/C; SizeArea_mm2: 1.28; SizeX_mm: 1.6; SizeY_mm: 0.8; SizeZ_mm: 1; EIA_Code: E192; U/M: EA; AEC Category: Q200
signal-integrity model Resistor
simulation model Resistor
footprint 0603
footprint 0603M
footprint 0603L
footprint 0603_HV
footprint 0603S
pins: 1, 2

## RT0603DRE07365RL
designator R?  ValueDisplayed: 365  (hidden comment: RT0603DRE07365RL)
RES, 365, 0.5%, 0.1 W, 0603; Manufacturer: Yageo America; CompType: Resistor; Value: 365; Value_Code: 365R; Tolerance_%: 0.5; Power_W: 0.1; Value2: 0.1W; VDC_V: 75; TempCo: 50 ppm/C; SizeArea_mm2: 1.28; SizeX_mm: 1.6; SizeY_mm: 0.8; SizeZ_mm: 1; EIA_Code: E192; U/M: EA; AEC Category: Q200
signal-integrity model Resistor
simulation model Resistor
footprint 0603
footprint 0603M
footprint 0603L
footprint 0603_HV
footprint 0603S
pins: 1, 2

## RT0603DRE07370KL
designator R?  ValueDisplayed: 370k  (hidden comment: RT0603DRE07370KL)
RES, 370 k, 0.5%, 0.1 W, 0603; Manufacturer: Yageo America; CompType: Resistor; Value: 370k; Res_ohm: 370000; Tolerance_%: 0.5; Power_W: 0.1; Value2: 0.1W; VDC_V: 75; TempCo: 50 ppm/C; SizeArea_mm2: 1.28; SizeX_mm: 1.6; SizeY_mm: 0.8; SizeZ_mm: 1; EIA_Code: E192; U/M: EA; AEC Category: Q200
signal-integrity model Resistor
simulation model Resistor
footprint 0603
footprint 0603M
footprint 0603L
footprint 0603_HV
footprint 0603S
pins: 1, 2

## RT0603DRE07370RL
designator R?  ValueDisplayed: 370  (hidden comment: RT0603DRE07370RL)
RES, 370, 0.5%, 0.1 W, 0603; Manufacturer: Yageo America; CompType: Resistor; Value: 370; Value_Code: 370R; Tolerance_%: 0.5; Power_W: 0.1; Value2: 0.1W; VDC_V: 75; TempCo: 50 ppm/C; SizeArea_mm2: 1.28; SizeX_mm: 1.6; SizeY_mm: 0.8; SizeZ_mm: 1; EIA_Code: E192; U/M: EA; AEC Category: Q200
signal-integrity model Resistor
simulation model Resistor
footprint 0603
footprint 0603M
footprint 0603L
footprint 0603_HV
footprint 0603S
pins: 1, 2

## RT0603DRE07374KL
designator R?  ValueDisplayed: 374k  (hidden comment: RT0603DRE07374KL)
RES, 374 k, 0.5%, 0.1 W, 0603; Manufacturer: Yageo America; CompType: Resistor; Value: 374k; Res_ohm: 374000; Tolerance_%: 0.5; Power_W: 0.1; Value2: 0.1W; VDC_V: 75; TempCo: 50 ppm/C; SizeArea_mm2: 1.28; SizeX_mm: 1.6; SizeY_mm: 0.8; SizeZ_mm: 1; EIA_Code: E192; U/M: EA; AEC Category: Q200
signal-integrity model Resistor
simulation model Resistor
footprint 0603
footprint 0603M
footprint 0603L
footprint 0603_HV
footprint 0603S
pins: 1, 2

## RT0603DRE07374RL
designator R?  ValueDisplayed: 374  (hidden comment: RT0603DRE07374RL)
RES, 374, 0.5%, 0.1 W, 0603; Manufacturer: Yageo America; CompType: Resistor; Value: 374; Value_Code: 374R; Tolerance_%: 0.5; Power_W: 0.1; Value2: 0.1W; VDC_V: 75; TempCo: 50 ppm/C; SizeArea_mm2: 1.28; SizeX_mm: 1.6; SizeY_mm: 0.8; SizeZ_mm: 1; EIA_Code: E192; U/M: EA; AEC Category: Q200
signal-integrity model Resistor
simulation model Resistor
footprint 0603
footprint 0603M
footprint 0603L
footprint 0603_HV
footprint 0603S
pins: 1, 2

## RT0603DRE07379KL
designator R?  ValueDisplayed: 379k  (hidden comment: RT0603DRE07379KL)
RES, 379 k, 0.5%, 0.1 W, 0603; Manufacturer: Yageo America; CompType: Resistor; Value: 379k; Res_ohm: 379000; Tolerance_%: 0.5; Power_W: 0.1; Value2: 0.1W; VDC_V: 75; TempCo: 50 ppm/C; SizeArea_mm2: 1.28; SizeX_mm: 1.6; SizeY_mm: 0.8; SizeZ_mm: 1; EIA_Code: E192; U/M: EA; AEC Category: Q200
signal-integrity model Resistor
simulation model Resistor
footprint 0603
footprint 0603M
footprint 0603L
footprint 0603_HV
footprint 0603S
pins: 1, 2

## RT0603DRE07379RL
designator R?  ValueDisplayed: 379  (hidden comment: RT0603DRE07379RL)
RES, 379, 0.5%, 0.1 W, 0603; Manufacturer: Yageo America; CompType: Resistor; Value: 379; Value_Code: 379R; Tolerance_%: 0.5; Power_W: 0.1; Value2: 0.1W; VDC_V: 75; TempCo: 50 ppm/C; SizeArea_mm2: 1.28; SizeX_mm: 1.6; SizeY_mm: 0.8; SizeZ_mm: 1; EIA_Code: E192; U/M: EA; AEC Category: Q200
signal-integrity model Resistor
simulation model Resistor
footprint 0603
footprint 0603M
footprint 0603L
footprint 0603_HV
footprint 0603S
pins: 1, 2

## RT0603DRE07383KL
designator R?  ValueDisplayed: 383k  (hidden comment: RT0603DRE07383KL)
RES, 383 k, 0.5%, 0.1 W, 0603; Manufacturer: Yageo America; CompType: Resistor; Value: 383k; Res_ohm: 383000; Tolerance_%: 0.5; Power_W: 0.1; Value2: 0.1W; VDC_V: 75; TempCo: 50 ppm/C; SizeArea_mm2: 1.28; SizeX_mm: 1.6; SizeY_mm: 0.8; SizeZ_mm: 1; EIA_Code: E192; U/M: EA; AEC Category: Q200
signal-integrity model Resistor
simulation model Resistor
footprint 0603
footprint 0603M
footprint 0603L
footprint 0603_HV
footprint 0603S
pins: 1, 2

## RT0603DRE07383RL
designator R?  ValueDisplayed: 383  (hidden comment: RT0603DRE07383RL)
RES, 383, 0.5%, 0.1 W, 0603; Manufacturer: Yageo America; CompType: Resistor; Value: 383; Value_Code: 383R; Tolerance_%: 0.5; Power_W: 0.1; Value2: 0.1W; VDC_V: 75; TempCo: 50 ppm/C; SizeArea_mm2: 1.28; SizeX_mm: 1.6; SizeY_mm: 0.8; SizeZ_mm: 1; EIA_Code: E192; U/M: EA; AEC Category: Q200
signal-integrity model Resistor
simulation model Resistor
footprint 0603
footprint 0603M
footprint 0603L
footprint 0603_HV
footprint 0603S
pins: 1, 2

## RT0603DRE07388KL
designator R?  ValueDisplayed: 388k  (hidden comment: RT0603DRE07388KL)
RES, 388 k, 0.5%, 0.1 W, 0603; Manufacturer: Yageo America; CompType: Resistor; Value: 388k; Res_ohm: 388000; Tolerance_%: 0.5; Power_W: 0.1; Value2: 0.1W; VDC_V: 75; TempCo: 50 ppm/C; SizeArea_mm2: 1.28; SizeX_mm: 1.6; SizeY_mm: 0.8; SizeZ_mm: 1; EIA_Code: E192; U/M: EA; AEC Category: Q200
signal-integrity model Resistor
simulation model Resistor
footprint 0603
footprint 0603M
footprint 0603L
footprint 0603_HV
footprint 0603S
pins: 1, 2

## RT0603DRE07388RL
designator R?  ValueDisplayed: 388  (hidden comment: RT0603DRE07388RL)
RES, 388, 0.5%, 0.1 W, 0603; Manufacturer: Yageo America; CompType: Resistor; Value: 388; Value_Code: 388R; Tolerance_%: 0.5; Power_W: 0.1; Value2: 0.1W; VDC_V: 75; TempCo: 50 ppm/C; SizeArea_mm2: 1.28; SizeX_mm: 1.6; SizeY_mm: 0.8; SizeZ_mm: 1; EIA_Code: E192; U/M: EA; AEC Category: Q200
signal-integrity model Resistor
simulation model Resistor
footprint 0603
footprint 0603M
footprint 0603L
footprint 0603_HV
footprint 0603S
pins: 1, 2

## RT0603DRE07392KL
designator R?  ValueDisplayed: 392k  (hidden comment: RT0603DRE07392KL)
RES, 392 k, 0.5%, 0.1 W, 0603; Manufacturer: Yageo America; CompType: Resistor; Value: 392k; Res_ohm: 392000; Tolerance_%: 0.5; Power_W: 0.1; Value2: 0.1W; VDC_V: 75; TempCo: 50 ppm/C; SizeArea_mm2: 1.28; SizeX_mm: 1.6; SizeY_mm: 0.8; SizeZ_mm: 1; EIA_Code: E192; U/M: EA; AEC Category: Q200
signal-integrity model Resistor
simulation model Resistor
footprint 0603
footprint 0603M
footprint 0603L
footprint 0603_HV
footprint 0603S
pins: 1, 2

## RT0603DRE07392RL
designator R?  ValueDisplayed: 392  (hidden comment: RT0603DRE07392RL)
RES, 392, 0.5%, 0.1 W, 0603; Manufacturer: Yageo America; CompType: Resistor; Value: 392; Value_Code: 392R; Tolerance_%: 0.5; Power_W: 0.1; Value2: 0.1W; VDC_V: 75; TempCo: 50 ppm/C; SizeArea_mm2: 1.28; SizeX_mm: 1.6; SizeY_mm: 0.8; SizeZ_mm: 1; EIA_Code: E192; U/M: EA; AEC Category: Q200
signal-integrity model Resistor
simulation model Resistor
footprint 0603
footprint 0603M
footprint 0603L
footprint 0603_HV
footprint 0603S
pins: 1, 2

## RT0603DRE07397KL
designator R?  ValueDisplayed: 397k  (hidden comment: RT0603DRE07397KL)
RES, 397 k, 0.5%, 0.1 W, 0603; Manufacturer: Yageo America; CompType: Resistor; Value: 397k; Res_ohm: 397000; Tolerance_%: 0.5; Power_W: 0.1; Value2: 0.1W; VDC_V: 75; TempCo: 50 ppm/C; SizeArea_mm2: 1.28; SizeX_mm: 1.6; SizeY_mm: 0.8; SizeZ_mm: 1; EIA_Code: E192; U/M: EA; AEC Category: Q200
signal-integrity model Resistor
simulation model Resistor
footprint 0603
footprint 0603M
footprint 0603L
footprint 0603_HV
footprint 0603S
pins: 1, 2

## RT0603DRE07397RL
designator R?  ValueDisplayed: 397  (hidden comment: RT0603DRE07397RL)
RES, 397, 0.5%, 0.1 W, 0603; Manufacturer: Yageo America; CompType: Resistor; Value: 397; Value_Code: 397R; Tolerance_%: 0.5; Power_W: 0.1; Value2: 0.1W; VDC_V: 75; TempCo: 50 ppm/C; SizeArea_mm2: 1.28; SizeX_mm: 1.6; SizeY_mm: 0.8; SizeZ_mm: 1; EIA_Code: E192; U/M: EA; AEC Category: Q200
signal-integrity model Resistor
simulation model Resistor
footprint 0603
footprint 0603M
footprint 0603L
footprint 0603_HV
footprint 0603S
pins: 1, 2

## RT0603DRE07402KL
designator R?  ValueDisplayed: 402k  (hidden comment: RT0603DRE07402KL)
RES, 402 k, 0.5%, 0.1 W, 0603; Manufacturer: Yageo America; CompType: Resistor; Value: 402k; Res_ohm: 402000; Tolerance_%: 0.5; Power_W: 0.1; Value2: 0.1W; VDC_V: 75; TempCo: 50 ppm/C; SizeArea_mm2: 1.28; SizeX_mm: 1.6; SizeY_mm: 0.8; SizeZ_mm: 1; EIA_Code: E192; U/M: EA; AEC Category: Q200
signal-integrity model Resistor
simulation model Resistor
footprint 0603
footprint 0603M
footprint 0603L
footprint 0603_HV
footprint 0603S
pins: 1, 2

## RT0603DRE07402RL
designator R?  ValueDisplayed: 402  (hidden comment: RT0603DRE07402RL)
RES, 402, 0.5%, 0.1 W, 0603; Manufacturer: Yageo America; CompType: Resistor; Value: 402; Value_Code: 402R; Tolerance_%: 0.5; Power_W: 0.1; Value2: 0.1W; VDC_V: 75; TempCo: 50 ppm/C; SizeArea_mm2: 1.28; SizeX_mm: 1.6; SizeY_mm: 0.8; SizeZ_mm: 1; EIA_Code: E192; U/M: EA; AEC Category: Q200
signal-integrity model Resistor
simulation model Resistor
footprint 0603
footprint 0603M
footprint 0603L
footprint 0603_HV
footprint 0603S
pins: 1, 2

## RT0603DRE07407KL
designator R?  ValueDisplayed: 407k  (hidden comment: RT0603DRE07407KL)
RES, 407 k, 0.5%, 0.1 W, 0603; Manufacturer: Yageo America; CompType: Resistor; Value: 407k; Res_ohm: 407000; Tolerance_%: 0.5; Power_W: 0.1; Value2: 0.1W; VDC_V: 75; TempCo: 50 ppm/C; SizeArea_mm2: 1.28; SizeX_mm: 1.6; SizeY_mm: 0.8; SizeZ_mm: 1; EIA_Code: E192; U/M: EA; AEC Category: Q200
signal-integrity model Resistor
simulation model Resistor
footprint 0603
footprint 0603M
footprint 0603L
footprint 0603_HV
footprint 0603S
pins: 1, 2

## RT0603DRE07407RL
designator R?  ValueDisplayed: 407  (hidden comment: RT0603DRE07407RL)
RES, 407, 0.5%, 0.1 W, 0603; Manufacturer: Yageo America; CompType: Resistor; Value: 407; Value_Code: 407R; Tolerance_%: 0.5; Power_W: 0.1; Value2: 0.1W; VDC_V: 75; TempCo: 50 ppm/C; SizeArea_mm2: 1.28; SizeX_mm: 1.6; SizeY_mm: 0.8; SizeZ_mm: 1; EIA_Code: E192; U/M: EA; AEC Category: Q200
signal-integrity model Resistor
simulation model Resistor
footprint 0603
footprint 0603M
footprint 0603L
footprint 0603_HV
footprint 0603S
pins: 1, 2

## RT0603DRE07412KL
designator R?  ValueDisplayed: 412k  (hidden comment: RT0603DRE07412KL)
RES, 412 k, 0.5%, 0.1 W, 0603; Manufacturer: Yageo America; CompType: Resistor; Value: 412k; Res_ohm: 412000; Tolerance_%: 0.5; Power_W: 0.1; Value2: 0.1W; VDC_V: 75; TempCo: 50 ppm/C; SizeArea_mm2: 1.28; SizeX_mm: 1.6; SizeY_mm: 0.8; SizeZ_mm: 1; EIA_Code: E192; U/M: EA; AEC Category: Q200
signal-integrity model Resistor
simulation model Resistor
footprint 0603
footprint 0603M
footprint 0603L
footprint 0603_HV
footprint 0603S
pins: 1, 2

## RT0603DRE07412RL
designator R?  ValueDisplayed: 412  (hidden comment: RT0603DRE07412RL)
RES, 412, 0.5%, 0.1 W, 0603; Manufacturer: Yageo America; CompType: Resistor; Value: 412; Value_Code: 412R; Tolerance_%: 0.5; Power_W: 0.1; Value2: 0.1W; VDC_V: 75; TempCo: 50 ppm/C; SizeArea_mm2: 1.28; SizeX_mm: 1.6; SizeY_mm: 0.8; SizeZ_mm: 1; EIA_Code: E192; U/M: EA; AEC Category: Q200
signal-integrity model Resistor
simulation model Resistor
footprint 0603
footprint 0603M
footprint 0603L
footprint 0603_HV
footprint 0603S
pins: 1, 2

## RT0603DRE07417KL
designator R?  ValueDisplayed: 417k  (hidden comment: RT0603DRE07417KL)
RES, 417 k, 0.5%, 0.1 W, 0603; Manufacturer: Yageo America; CompType: Resistor; Value: 417k; Res_ohm: 417000; Tolerance_%: 0.5; Power_W: 0.1; Value2: 0.1W; VDC_V: 75; TempCo: 50 ppm/C; SizeArea_mm2: 1.28; SizeX_mm: 1.6; SizeY_mm: 0.8; SizeZ_mm: 1; EIA_Code: E192; U/M: EA; AEC Category: Q200
signal-integrity model Resistor
simulation model Resistor
footprint 0603
footprint 0603M
footprint 0603L
footprint 0603_HV
footprint 0603S
pins: 1, 2

## RT0603DRE07417RL
designator R?  ValueDisplayed: 417  (hidden comment: RT0603DRE07417RL)
RES, 417, 0.5%, 0.1 W, 0603; Manufacturer: Yageo America; CompType: Resistor; Value: 417; Value_Code: 417R; Tolerance_%: 0.5; Power_W: 0.1; Value2: 0.1W; VDC_V: 75; TempCo: 50 ppm/C; SizeArea_mm2: 1.28; SizeX_mm: 1.6; SizeY_mm: 0.8; SizeZ_mm: 1; EIA_Code: E192; U/M: EA; AEC Category: Q200
signal-integrity model Resistor
simulation model Resistor
footprint 0603
footprint 0603M
footprint 0603L
footprint 0603_HV
footprint 0603S
pins: 1, 2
